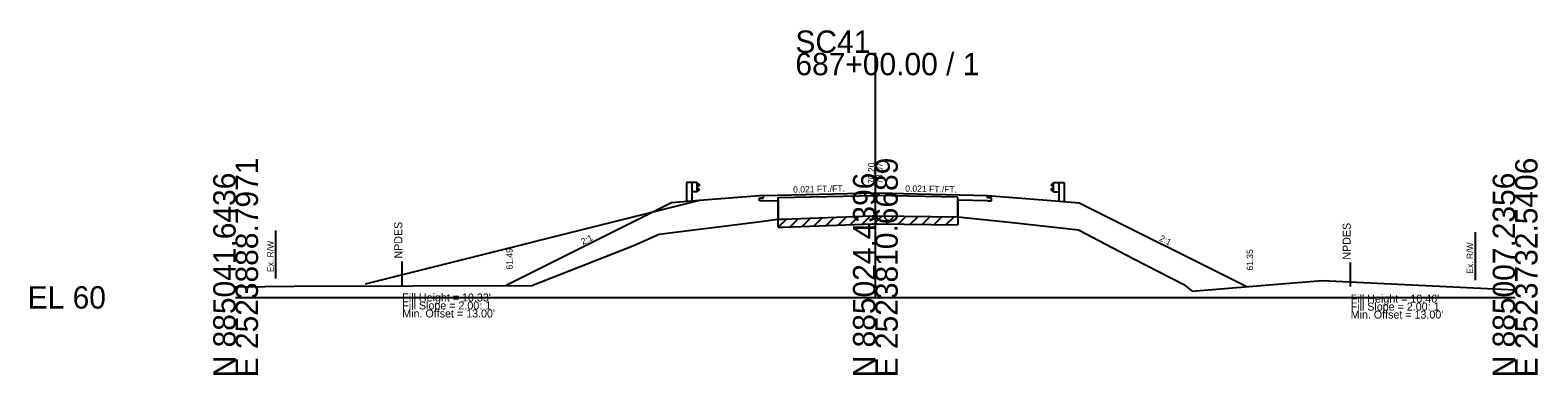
# Model space of a CAD drawing. Extents: x -26 to 183, y -10 to 24021.
# Drawn here: x -25.7 to 162.8, y 15490.3 to 15533.4 of the extents above; entities that cross this region are included whole.
import ezdxf

# ---------------------------------------------------------------- set-up
doc = ezdxf.new("R2010")
doc.units = 0
for name, color, linetype in [('RD_GPK_XS_Cell', 7, 'Continuous'), ('RD_XS_Base', 7, 'Continuous'), ('RD_XS_Buildup', 7, 'Continuous'), ('RD_XS_EarthShd', 7, 'Continuous'), ('RD_XS_ExGround', 7, 'Continuous'), ('RD_XS_ExPaveRet', 7, 'Continuous'), ('RD_XS_ExRW', 7, 'Continuous'), ('RD_XS_GR', 7, 'Continuous'), ('RD_XS_NPDES', 7, 'Continuous'), ('RD_XS_Pave', 7, 'Continuous'), ('RD_XS_TieSlope', 7, 'Continuous'), ('RD_XS_TX_Elev_EX', 7, 'Continuous'), ('RD_XS_TX_Elev_PR', 7, 'Continuous'), ('RD_XS_TX_Slope', 7, 'Continuous'), ('RD_XS_TX_Warning', 7, 'Continuous')]:
    doc.layers.add(name, color=color, linetype=linetype)

msp = doc.modelspace()

# ---------------------------------------------------------------- linework, layer by layer
at = {"layer": 'RD_GPK_XS_Cell'}
for p, q in [((80, 15500), (80, 15530.6)), ((0, 15500), (80, 15500)), ((80, 15500), (160, 15500))]:
    msp.add_line(p, q, dxfattribs=at)
at = {"layer": 'RD_XS_Base'}
for p, q in [((66, 15512.09), (67.86, 15512.13)), ((67.86, 15512.13), (67.86, 15509.78)), ((90.33, 15512.17), (90.33, 15510.09)), ((94, 15512.09), (90.33, 15512.17))]:
    msp.add_line(p, q, dxfattribs=at)
at = {"layer": 'RD_XS_Buildup'}
for p, q in [((67.86, 15512.49), (80, 15512.75)), ((67.86, 15509.78), (67.86, 15512.49)), ((90.33, 15512.53), (80, 15512.75)), ((90.33, 15510.09), (90.33, 15512.53))]:
    msp.add_line(p, q, dxfattribs=at)
at = {"layer": 'RD_XS_EarthShd'}
for p, q in [((66, 15512.77), (58, 15512.11)), ((94, 15512.77), (102, 15512.11)), ((58, 15512.11), (54.5, 15511.82)), ((102, 15512.11), (105.5, 15511.82))]:
    msp.add_line(p, q, dxfattribs=at)
at = {"layer": 'RD_XS_ExGround'}
for p, q in [((52.98, 15507.92), (64.99, 15509.42)), ((64.99, 15509.42), (67.86, 15509.78)), ((67.86, 15509.78), (68.46, 15509.8)), ((68.46, 15509.8), (79.61, 15510.2)), ((79.61, 15510.2), (80.25, 15510.2)), ((80.25, 15510.2), (90.33, 15510.09)), ((90.33, 15510.09), (97.51, 15509.33)), ((97.51, 15509.33), (105.38, 15508.46)), ((49.69, 15506.44), (52.98, 15507.92)), ((105.38, 15508.46), (112.22, 15504.87)), ((37.02, 15501.5), (49.69, 15506.44)), ((112.22, 15504.87), (118.58, 15501.6)), ((0, 15501.33), (7.32, 15501.39)), ((7.32, 15501.39), (37.02, 15501.5)), ((118.58, 15501.6), (119.62, 15500.8)), ((119.62, 15500.8), (124.15, 15501.17)), ((124.15, 15501.17), (135.88, 15502.12)), ((135.88, 15502.12), (160, 15500.93))]:
    msp.add_line(p, q, dxfattribs=at)
at = {"layer": 'RD_XS_ExPaveRet'}
for p, q in [((67.86, 15508.78), (68.9, 15509.81)), ((67.86, 15508.78), (67.86, 15509.78)), ((67.86, 15508.78), (68.46, 15508.8)), ((68.46, 15508.8), (79.61, 15509.2)), ((69.36, 15508.83), (70.4, 15509.87)), ((70.86, 15508.88), (71.9, 15509.92)), ((72.36, 15508.94), (73.4, 15509.98)), ((73.86, 15508.99), (74.9, 15510.03)), ((75.36, 15509.05), (76.4, 15510.08)), ((76.86, 15509.1), (77.9, 15510.14)), ((78.36, 15509.16), (79.4, 15510.19)), ((79.61, 15509.2), (80.25, 15509.2)), ((79.86, 15509.2), (80.85, 15510.19)), ((80.25, 15509.2), (90.33, 15509.09)), ((81.36, 15509.18), (82.35, 15510.17)), ((82.86, 15509.17), (83.85, 15510.16)), ((84.36, 15509.15), (85.35, 15510.14)), ((85.86, 15509.14), (86.85, 15510.13)), ((87.36, 15509.12), (88.35, 15510.11)), ((88.86, 15509.11), (89.85, 15510.1)), ((90.33, 15510.09), (90.33, 15509.09))]:
    msp.add_line(p, q, dxfattribs=at)
at = {"layer": 'RD_XS_ExRW'}
for p, q in [((5, 15508.37), (5, 15502.37)), ((155, 15508.17), (155, 15502.17))]:
    msp.add_line(p, q, dxfattribs=at)
at = {"layer": 'RD_XS_GR'}
for p, q in [((56.4, 15514.36), (56.4, 15511.97)), ((57.06, 15514.36), (56.4, 15514.36)), ((57.06, 15514.36), (57.06, 15512.03)), ((57.73, 15514.36), (57.06, 15514.36)), ((57.73, 15513.19), (57.73, 15514.36)), ((102.27, 15513.19), (102.27, 15514.36)), ((102.27, 15514.36), (102.94, 15514.36)), ((102.94, 15514.36), (102.94, 15512.03)), ((102.94, 15514.36), (103.6, 15514.36)), ((103.6, 15514.36), (103.6, 15511.97)), ((57.73, 15513.19), (57.06, 15513.19)), ((57.73, 15514.28), (58, 15514.08)), ((58, 15514.03), (57.73, 15513.83)), ((58, 15513.51), (57.73, 15513.71)), ((57.73, 15513.26), (58, 15513.46)), ((58, 15514.08), (58, 15514.03)), ((58, 15513.46), (58, 15513.51)), ((102.27, 15514.28), (102, 15514.08)), ((102, 15514.08), (102, 15514.03)), ((102, 15514.03), (102.27, 15513.83)), ((102, 15513.51), (102.27, 15513.71)), ((102, 15513.46), (102, 15513.51)), ((102.27, 15513.26), (102, 15513.46)), ((102.27, 15513.19), (102.94, 15513.19))]:
    msp.add_line(p, q, dxfattribs=at)
at = {"layer": 'RD_XS_NPDES'}
for p, q in [((20.84, 15501.49), (20.84, 15504.49)), ((139.43, 15501.35), (139.43, 15504.35))]:
    msp.add_line(p, q, dxfattribs=at)
at = {"layer": 'RD_XS_Pave'}
for p, q in [((66, 15512.77), (80, 15513.07)), ((66, 15512.45), (66, 15512.77)), ((80, 15513.07), (94, 15512.77)), ((94, 15512.45), (94, 15512.77)), ((58, 15512.11), (16.21, 15501.66)), ((65.5, 15512.44), (66, 15512.45)), ((65.5, 15512.08), (65.5, 15512.44)), ((66, 15512.09), (65.5, 15512.08)), ((94.5, 15512.44), (94, 15512.45)), ((94, 15512.09), (94.5, 15512.08)), ((94.5, 15512.08), (94.5, 15512.44))]:
    msp.add_line(p, q, dxfattribs=at)
at = {"layer": 'RD_XS_TieSlope'}
for p, q in [((54.5, 15511.82), (33.84, 15501.49)), ((105.5, 15511.82), (126.43, 15501.35))]:
    msp.add_line(p, q, dxfattribs=at)

# ---------------------------------------------------------------- texts
at = {"layer": 'RD_GPK_XS_Cell'}
for s, p in [('SC41', (70, 15530.6)), ('687+00.00 / 1', (70, 15527.8)), ('EL 60', (-26, 15498.6))]:
    msp.add_text(s, height=2.8, dxfattribs=at).set_placement(p)
for s, p in [('E 2523888.7971', (2.8, 15490)), ('E 2523810.6689', (82.8, 15490)), ('E 2523732.5406', (162.8, 15490)), ('N 885041.6436', (0, 15490)), ('N 885024.4396', (80, 15490)), ('N 885007.2356', (160, 15490))]:
    msp.add_text(s, height=2.8, rotation=90, dxfattribs=at).set_placement(p)
at = {"layer": 'RD_XS_ExRW'}
for p in [(4.75, 15503.16), (154.75, 15502.96)]:
    msp.add_text('Ex. R/W ', height=0.8, rotation=90, dxfattribs=at).set_placement(p)
at = {"layer": 'RD_XS_TX_Elev_EX'}
msp.add_text('70.20', height=0.8, rotation=90, dxfattribs=at).set_placement((79.9, 15514.2))
at = {"layer": 'RD_XS_TX_Elev_PR'}
for s, p in [('73.07', (80.9, 15514.2)), ('61.49', (34.64, 15503.49)), ('61.35', (127.23, 15503.35))]:
    msp.add_text(s, height=0.8, rotation=90, dxfattribs=at).set_placement(p)
at = {"layer": 'RD_XS_TX_Slope'}
for s, rotation, p in [('0.021 FT./FT.', 1.1916, (69.72, 15513.1)), ('0.021 FT./FT.', 358.8084, (83.73, 15513.24)), ('2:1', 26.5651, (43.42, 15506.55)), ('2:1', 333.4349, (115.43, 15507.13))]:
    msp.add_text(s, height=0.8, rotation=rotation, dxfattribs=at).set_placement(p)
at = {"layer": 'RD_XS_TX_Warning'}
for p in [(20.84, 15504.49), (139.43, 15504.35)]:
    msp.add_text(' NPDES', height=1, rotation=90, dxfattribs=at).set_placement(p)
for s, p in [("Fill Height = 10.33' ", (20.84, 15499.49)), ('Fill Slope = 2.00: 1', (20.84, 15498.49)), ("Fill Height = 10.46' ", (139.43, 15499.35)), ('Fill Slope = 2.00: 1', (139.43, 15498.35)), ("Min. Offset = 13.00' ", (20.84, 15497.49)), ("Min. Offset = 13.00' ", (139.43, 15497.35))]:
    msp.add_text(s, height=1, dxfattribs=at).set_placement(p)

doc.saveas('drawing.dxf')
